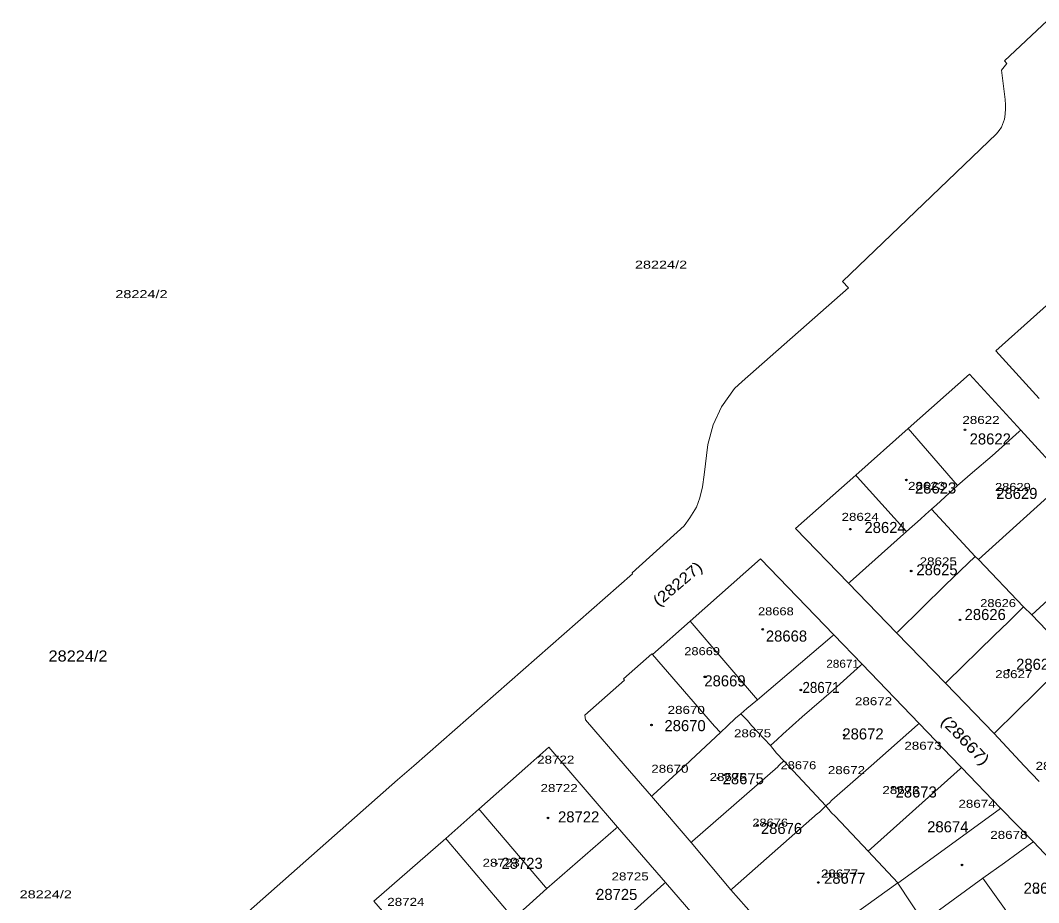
# Model space of a CAD drawing. Extents: x 650553 to 652508, y 239277 to 241647.
# Drawn here: x 650877.5 to 651208.2, y 240705.5 to 240992.1 of the extents above; entities that cross this region are included whole.
import ezdxf

# ---------------------------------------------------------------- set-up
doc = ezdxf.new("R2010")
doc.units = 0
doc.header["$PDMODE"] = 32
doc.header["$PDSIZE"] = 0.5
for name, color, linetype in [('19', 7, 'Continuous'), ('20', 7, 'Continuous'), ('6', 7, 'Continuous')]:
    doc.layers.add(name, color=color, linetype=linetype)
doc.layers.add('3', color=7, linetype='Continuous', lineweight=13)
doc.layers.add('5', color=7, linetype='Continuous', lineweight=13)

msp = doc.modelspace()

# ---------------------------------------------------------------- linework, layer by layer
at = {"layer": '3'}
for points in [[(650909.64, 240665.65), (651000, 240745.41), (651001.47, 240746.7), (651005.22, 240750), (651076.27, 240812.38), (651076.13, 240812.69), (651093.1, 240827.92), (651094.88, 240830.47), (651097.1, 240833.98), (651098.17, 240837.05), (651098.98, 240840.6), (651099.5, 240844.5), (651100.77, 240854.38), (651102.43, 240860.75), (651105.15, 240866.61), (651109.42, 240872.55), (651111.83, 240874.77), (651146.4, 240905.19), (651144.44, 240907.26), (651194.49, 240955.29), (651195.33, 240956.31), (651196.11, 240957.4), (651196.73, 240959.15), (651197.07, 240960.05), (651197.25, 240961.66), (651197.42, 240963.46), (651197.44, 240964.69), (651197.26, 240966.42), (651196.09, 240975.92), (651197.79, 240978.12), (651197.1, 240978.93), (651211.069, 240992.128)], [(651208.31, 240869.33), (651194.27, 240884.81), (651220.87, 240908.63)], [(651165.74, 240859.56), (651185.75, 240877.17), (651202.38, 240859), (651217.18, 240842.81), (651233.79, 240824.62), (651250.56, 240806.18), (651267.52, 240787.73)], [(651146.4, 240809.27), (651129.19, 240827.02), (651148.74, 240844.39), (651165.74, 240859.56)], [(651094.95, 240796.93), (651117.8, 240817.22), (651141.65, 240792.52), (651150.86, 240783.02), (651169.34, 240763.7)], [(651208.28, 240744.9), (651203.48, 240750), (651193.67, 240760.43), (651177.86, 240776.79), (651162.01, 240793.16), (651146.4, 240809.27)], [(651082.48, 240740.13), (651073.9, 240750), (651060.97, 240764.88), (651060.76, 240766.4), (651073.72, 240777.79), (651073.35, 240778.24), (651082.51, 240786.38), (651082.82, 240786.1), (651094.95, 240796.93)], [(651169.34, 240763.7), (651182.59, 240750), (651183.12, 240749.45), (651195.81, 240736.18), (651206.48, 240725.3)], [(651026.36, 240735.92), (651042.33, 240750), (651049.14, 240756), (651054.28, 240750), (651071.37, 240730.08), (651086.99, 240712.03), (651099.98, 240696.99), (651115.95, 240678.49), (651125.85, 240666.99)], [(651175.31, 240668.77), (651158.22, 240655.77), (651157.18, 240655.38), (651155.68, 240655.72), (651138.16, 240675.55), (651128.09, 240687.18), (651108.21, 240709.64), (651095.3, 240725), (651082.48, 240740.13)], [(650992.27, 240705.99), (651015.67, 240726.31), (651026.36, 240735.92)], [(651206.48, 240725.3), (651223.8, 240706.84), (651205.18, 240692.18), (651190.09, 240680.31), (651175.31, 240668.77)], [(651106.26, 240614.46), (651085.2, 240598.08), (651066.5, 240619.71), (651054.18, 240634.25), (651039.57, 240651.25), (651030.43, 240661.99), (651014.76, 240679.98), (650992.27, 240705.99)]]:
    msp.add_lwpolyline(points, dxfattribs=at)
at = {"layer": '5'}
for p, q in [((651219, 240785.29), (651205.99, 240798.98)), ((651123.86, 240750.19), (651123.72, 240750)), ((651125.37, 240751.63), (651123.86, 240750.19)), ((651126.9, 240750), (651139.09, 240736.96)), ((651190.04, 240713.5), (651197.03, 240718.49))]:
    msp.add_line(p, q, dxfattribs=at)
for points in [[(651187.57, 240817.95), (651174.67, 240831.92), (651173.31, 240833.31), (651175.02, 240834.79), (651181.83, 240841.04), (651165.74, 240859.56)], [(651193.01, 240850.63), (651201.88, 240858.553), (651202.38, 240859)], [(651181.83, 240841.04), (651186.69, 240845.2), (651193.01, 240850.63)], [(651165.27, 240826.07), (651149.191, 240843.89), (651148.74, 240844.39)], [(651188.61, 240817.03), (651216.68, 240842.359), (651217.18, 240842.81)], [(651173.31, 240833.31), (651171.42, 240831.64), (651169.75, 240830.14), (651165.27, 240826.07)], [(651165.27, 240826.07), (651146.9, 240809.715), (651146.4, 240809.27)], [(651205.99, 240798.98), (651233.29, 240824.159), (651233.79, 240824.62)], [(651203.28, 240801.63), (651188.61, 240817.03), (651187.57, 240817.95), (651177.93, 240808.71)], [(651177.93, 240808.71), (651162.51, 240793.648), (651162.01, 240793.16)], [(651205.99, 240798.98), (651203.28, 240801.63), (651198.26, 240796.66), (651193.77, 240792.44)], [(651141.65, 240792.52), (651141.15, 240792.096), (651116.82, 240771.44), (651094.95, 240796.93)], [(651193.77, 240792.44), (651178.36, 240777.282), (651177.86, 240776.79)], [(651111.43, 240766.9), (651109.77, 240765.42), (651107.16, 240763), (651104.84, 240760.81), (651102.91, 240762.8), (651082.82, 240786.1)], [(651150.86, 240783.02), (651150.36, 240782.574), (651141.53, 240774.69), (651131.36, 240765.84), (651125.1, 240760.22), (651123.28, 240758.54), (651121.05, 240756.61), (651123.07, 240754.05), (651125.37, 240751.63), (651126.9, 240750)], [(651213.96, 240780.44), (651194.17, 240760.923), (651193.67, 240760.43)], [(651121.05, 240756.61), (651114.95, 240763.06), (651113.61, 240764.66), (651111.43, 240766.9), (651113.38, 240768.57), (651116.82, 240771.44)], [(651169.34, 240763.7), (651168.84, 240763.26), (651153.76, 240750)], [(651104.84, 240760.81), (651096.8, 240753.28), (651093.23, 240750)], [(651082.48, 240740.13), (651082.98, 240740.589), (651093.23, 240750)], [(651095.3, 240725), (651095.8, 240725.438), (651123.42, 240749.62), (651123.72, 240750)], [(651139.09, 240736.96), (651140.28, 240737.98), (651141.05, 240738.82), (651153.76, 240750)], [(651152.81, 240722.25), (651182.62, 240749.001), (651183.12, 240749.45)], [(651026.36, 240735.92), (651026.786, 240735.42), (651047.984, 240710.56), (651048.41, 240710.06)], [(651139.09, 240736.96), (651136.85, 240734.85), (651136.33, 240734.48)], [(651139.09, 240736.96), (651140.92, 240734.71), (651142.13, 240733.64), (651152.81, 240722.25), (651162.42, 240711.91)], [(651162.444, 240711.874), (651195.31, 240735.816), (651195.81, 240736.18)], [(651136.33, 240734.48), (651108.71, 240710.082), (651108.21, 240709.64)], [(651048.41, 240710.06), (651070.87, 240729.644), (651071.37, 240730.08)], [(651015.67, 240726.31), (651016.093, 240725.81), (651037.177, 240700.89), (651037.6, 240700.39)], [(651197.03, 240718.49), (651205.98, 240724.94), (651206.48, 240725.3)], [(651058.77, 240686.76), (651086.49, 240711.582), (651086.99, 240712.03)], [(651190.04, 240713.5), (651174.72, 240702.34), (651176.15, 240700.47)], [(651190.04, 240713.5), (651204.825, 240692.68), (651205.18, 240692.18)], [(651014.76, 240679.98), (651015.26, 240680.427), (651037.6, 240700.39), (651042.88, 240705.04), (651048.41, 240710.06)], [(651128.09, 240687.18), (651128.59, 240687.54), (651162.42, 240711.91)], [(651170.71, 240699.36), (651162.444, 240711.874), (651162.42, 240711.91)]]:
    msp.add_lwpolyline(points, dxfattribs=at)
at = {"layer": '6'}
for p in [(651184.21, 240859.105), (651165.224, 240842.815), (651195.2, 240838.015), (651146.979, 240826.83), (651166.752, 240813.235), (651182.649, 240797.37), (651118.542, 240794.33), (651099.75, 240778.87), (651198.372, 240781.03), (651130.944, 240774.565), (651082.45, 240763.255), (651144.986, 240759.99), (651104.024, 240745.95), (651160.839, 240742.975), (651048.832, 240733.03), (651116.857, 240730.635), (651175.209, 240730.662), (651032.039, 240718.155), (651183.28, 240717.77), (651136.616, 240712.07), (651207.719, 240708.74), (651064.781, 240708.42)]:
    msp.add_point(p, dxfattribs=at)

# ---------------------------------------------------------------- texts
at = {"layer": '19'}
for s, p in [('28622', (651185.746, 240854.349)), ('28623', (651168.007, 240838.418)), ('28629', (651194.369, 240836.653)), ('28624', (651151.599, 240825.585)), ('28625', (651168.451, 240811.867)), ('28626', (651184.11, 240797.319)), ('28668', (651119.584, 240790.314)), ('28627', (651200.849, 240781.154)), ('28669', (651099.605, 240775.766)), ('28670', (651086.647, 240761.218)), ('28672', (651144.423, 240758.523)), ('28675', (651105.546, 240743.975)), ('28673', (651161.702, 240739.665)), ('28722', (651052.089, 240731.582)), ('28674', (651171.962, 240728.349)), ('28676', (651117.965, 240727.81)), ('28723', (651033.73, 240716.495)), ('28677', (651138.484, 240711.646)), ('28679', (651203.28, 240708.413)), ('28725', (651064.456, 240706.385))]:
    msp.add_text(s, height=3.6, dxfattribs=at).set_placement(p)
for s, rotation, width, p in [('(28227)', 40.374, 1.15, (651084.794, 240801.537)), ('(28667)', 314.043, 1.2, (651176.116, 240764.146))]:
    msp.add_text(s, height=3.6, rotation=rotation, dxfattribs=dict(at, width=width)).set_placement(p)
for s, width, p in [('28224/2', 1.1, (650886.652, 240783.84)), ('28671', 0.9, (651131.464, 240773.611))]:
    msp.add_text(s, height=3.6, dxfattribs=dict(at, width=width)).set_placement(p)
at = {"layer": '20'}
for s, width, p in [('28224/2', 1.35, (651077.053, 240911.454)), ('28224/2', 1.35, (650908.337, 240901.902)), ('28622', 1.25, (651183.39, 240861.02)), ('28623', 1.25, (651165.749, 240839.599)), ('28629', 1.2, (651194.002, 240839.255)), ('28624', 1.25, (651144.155, 240829.534)), ('28625', 1.25, (651169.506, 240815.066)), ('28668', 1.2, (651117.028, 240798.854)), ('28626', 1.2, (651189.18, 240801.523)), ('28669', 1.2, (651093.083, 240785.903)), ('28671', 1.1, (651139.186, 240781.821)), ('28627', 1.25, (651194.044, 240778.437)), ('28672', 1.25, (651148.496, 240769.645)), ('28670', 1.25, (651087.678, 240766.828)), ('28675', 1.25, (651109.219, 240759.227)), ('28673', 1.25, (651164.556, 240755.183)), ('28722', 1.25, (651045.31, 240750.681)), ('28670', 1.25, (651082.365, 240747.709)), ('28676', 1.2, (651124.347, 240748.852)), ('28672', 1.25, (651139.7, 240747.267)), ('28628', 1.25, (651207.16, 240748.654)), ('28675', 1.25, (651101.308, 240745.044)), ('28722', 1.25, (651046.404, 240741.437)), ('28673', 1.25, (651157.409, 240740.793)), ('28674', 1.25, (651182.109, 240736.328)), ('28676', 1.2, (651115.184, 240730.209)), ('28678', 1.25, (651192.439, 240726.221)), ('28723', 1.25, (651027.579, 240717.182)), ('28725', 1.25, (651069.456, 240712.735)), ('28677', 1.25, (651137.46, 240713.682)), ('28224/2', 1.35, (650877.267, 240706.907)), ('28724', 1.25, (650996.646, 240704.47))]:
    msp.add_text(s, height=2.6, dxfattribs=dict(at, width=width)).set_placement(p)

doc.saveas('drawing.dxf')
